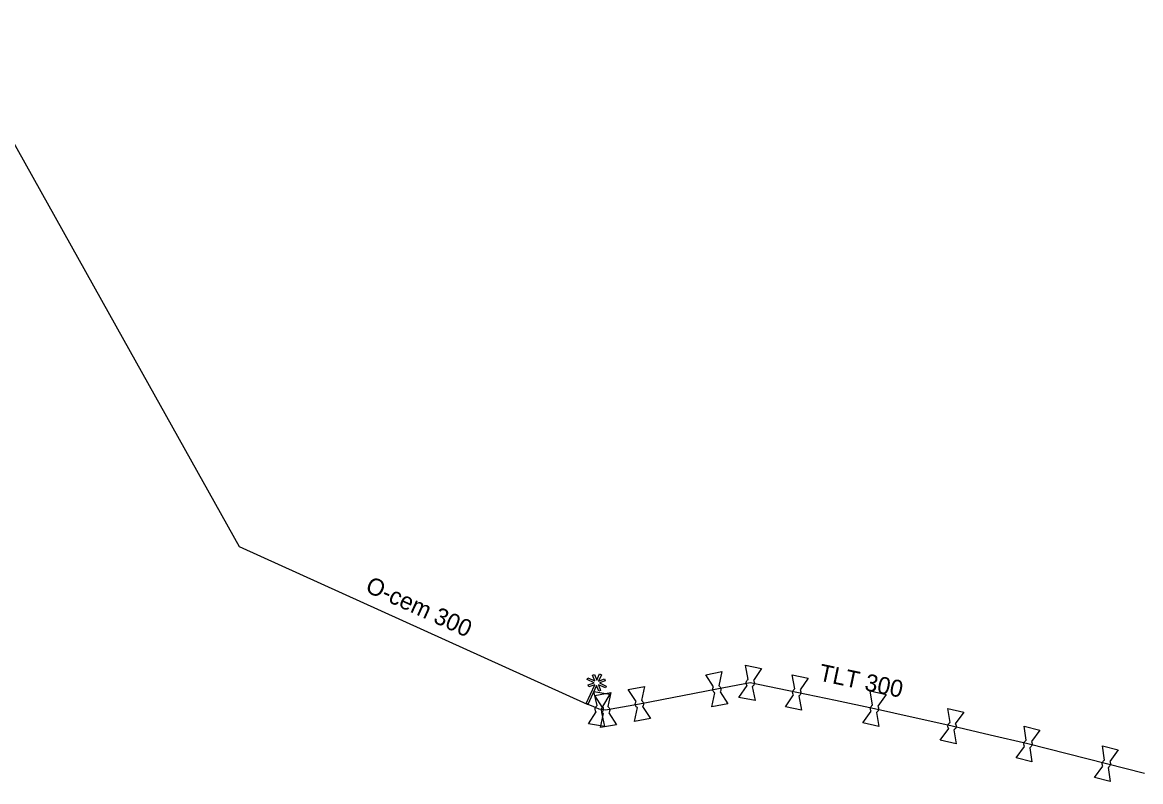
# Model space of a CAD drawing. Extents: x -638315 to -636370, y -1116147 to -1115110.
# Drawn here: x -637339.1 to -637253.7, y -1116037.8 to -1115979.8 of the extents above; entities that cross this region are included whole.
import ezdxf

# ---------------------------------------------------------------- set-up
doc = ezdxf.new("R2010")
doc.units = 0
for name, color, linetype in [('Default', 7, 'Continuous'), ('VP Lomový bod', 7, 'Continuous'), ('VP Změna materiálu', 7, 'Continuous'), ('VP Řad', 7, 'Continuous'), ('VP Řad - popis', 7, 'Continuous')]:
    doc.layers.add(name, color=color, linetype=linetype)

msp = doc.modelspace()

# ---------------------------------------------------------------- linework, layer by layer
at = {"layer": 'Default'}
for points in [[(-637286.238, -1116031.042), (-637286.282, -1116031.016), (-637286.317, -1116030.975), (-637286.372, -1116030.908), (-637286.387, -1116030.828), (-637286.402, -1116030.747), (-637286.375, -1116030.668), (-637286.357, -1116030.616), (-637286.324, -1116030.575)], [(-637285.923, -1116030.5), (-637285.878, -1116030.526), (-637285.842, -1116030.568), (-637285.788, -1116030.632), (-637285.773, -1116030.712), (-637285.758, -1116030.793), (-637285.786, -1116030.875), (-637285.802, -1116030.925), (-637285.836, -1116030.966)], [(-637283.778, -1116030.483), (-637283.81, -1116030.441), (-637283.827, -1116030.39), (-637283.853, -1116030.308), (-637283.836, -1116030.228), (-637283.82, -1116030.148), (-637283.765, -1116030.084), (-637283.729, -1116030.043), (-637283.683, -1116030.017)], [(-637283.283, -1116030.098), (-637283.25, -1116030.14), (-637283.234, -1116030.192), (-637283.207, -1116030.272), (-637283.224, -1116030.352), (-637283.24, -1116030.432), (-637283.297, -1116030.498), (-637283.331, -1116030.538), (-637283.378, -1116030.564)], [(-637280.23, -1116031.201), (-637280.261, -1116031.159), (-637280.278, -1116031.108), (-637280.303, -1116031.026), (-637280.286, -1116030.946), (-637280.269, -1116030.866), (-637280.213, -1116030.802), (-637280.177, -1116030.761), (-637280.131, -1116030.736)], [(-637279.732, -1116030.82), (-637279.699, -1116030.862), (-637279.683, -1116030.914), (-637279.657, -1116030.994), (-637279.674, -1116031.074), (-637279.691, -1116031.154), (-637279.749, -1116031.22), (-637279.783, -1116031.26), (-637279.83, -1116031.285)], [(-637295.301, -1116032.482), (-637295.334, -1116032.442), (-637295.353, -1116032.392), (-637295.382, -1116032.31), (-637295.368, -1116032.23), (-637295.355, -1116032.149), (-637295.302, -1116032.083), (-637295.268, -1116032.041), (-637295.223, -1116032.013)], [(-637294.821, -1116032.079), (-637294.786, -1116032.119), (-637294.768, -1116032.171), (-637294.738, -1116032.25), (-637294.752, -1116032.33), (-637294.765, -1116032.411), (-637294.819, -1116032.479), (-637294.852, -1116032.521), (-637294.897, -1116032.548)], [(-637294.73, -1116032.63), (-637294.775, -1116032.604), (-637294.809, -1116032.563), (-637294.863, -1116032.495), (-637294.878, -1116032.415), (-637294.892, -1116032.334), (-637294.864, -1116032.255), (-637294.846, -1116032.203), (-637294.812, -1116032.163)], [(-637294.411, -1116032.091), (-637294.365, -1116032.118), (-637294.33, -1116032.16), (-637294.277, -1116032.225), (-637294.262, -1116032.305), (-637294.248, -1116032.386), (-637294.277, -1116032.468), (-637294.294, -1116032.518), (-637294.328, -1116032.559)], [(-637292.147, -1116032.172), (-637292.192, -1116032.146), (-637292.227, -1116032.106), (-637292.282, -1116032.039), (-637292.297, -1116031.959), (-637292.312, -1116031.878), (-637292.285, -1116031.799), (-637292.268, -1116031.747), (-637292.235, -1116031.706)], [(-637291.834, -1116031.629), (-637291.788, -1116031.655), (-637291.753, -1116031.697), (-637291.698, -1116031.761), (-637291.683, -1116031.841), (-637291.668, -1116031.922), (-637291.695, -1116032.004), (-637291.712, -1116032.054), (-637291.745, -1116032.096)], [(-637274.302, -1116032.447), (-637274.333, -1116032.405), (-637274.349, -1116032.354), (-637274.373, -1116032.271), (-637274.355, -1116032.192), (-637274.337, -1116032.112), (-637274.28, -1116032.049), (-637274.244, -1116032.009), (-637274.197, -1116031.984)], [(-637273.799, -1116032.074), (-637273.767, -1116032.116), (-637273.752, -1116032.168), (-637273.727, -1116032.249), (-637273.745, -1116032.328), (-637273.763, -1116032.408), (-637273.821, -1116032.473), (-637273.856, -1116032.512), (-637273.903, -1116032.537)], [(-637268.384, -1116033.775), (-637268.414, -1116033.733), (-637268.429, -1116033.682), (-637268.452, -1116033.598), (-637268.434, -1116033.519), (-637268.415, -1116033.439), (-637268.358, -1116033.377), (-637268.321, -1116033.337), (-637268.274, -1116033.313)], [(-637267.877, -1116033.406), (-637267.846, -1116033.449), (-637267.83, -1116033.501), (-637267.807, -1116033.582), (-637267.825, -1116033.661), (-637267.844, -1116033.741), (-637267.903, -1116033.805), (-637267.938, -1116033.844), (-637267.985, -1116033.868)], [(-637262.587, -1116035.131), (-637262.617, -1116035.088), (-637262.631, -1116035.036), (-637262.653, -1116034.953), (-637262.633, -1116034.873), (-637262.613, -1116034.794), (-637262.555, -1116034.733), (-637262.517, -1116034.694), (-637262.47, -1116034.67)], [(-637262.074, -1116034.77), (-637262.044, -1116034.813), (-637262.029, -1116034.866), (-637262.007, -1116034.947), (-637262.027, -1116035.027), (-637262.047, -1116035.106), (-637262.107, -1116035.169), (-637262.143, -1116035.207), (-637262.191, -1116035.231)], [(-637256.608, -1116036.64), (-637256.637, -1116036.597), (-637256.652, -1116036.546), (-637256.673, -1116036.462), (-637256.653, -1116036.383), (-637256.633, -1116036.303), (-637256.574, -1116036.243), (-637256.536, -1116036.203), (-637256.489, -1116036.18)], [(-637256.094, -1116036.281), (-637256.063, -1116036.324), (-637256.049, -1116036.377), (-637256.027, -1116036.458), (-637256.047, -1116036.537), (-637256.067, -1116036.617), (-637256.128, -1116036.679), (-637256.164, -1116036.718), (-637256.211, -1116036.741)]]:
    msp.add_open_spline(points, degree=3, dxfattribs=at)
at = {"layer": 'VP Lomový bod'}
for points in [[(-637283.683, -1116030.017), (-637283.894, -1116028.941), (-637282.669, -1116029.189), (-637283.283, -1116030.098)], [(-637286.324, -1116030.575), (-637286.925, -1116029.657), (-637285.697, -1116029.426), (-637285.923, -1116030.5)], [(-637280.131, -1116030.736), (-637280.334, -1116029.658), (-637279.111, -1116029.916), (-637279.732, -1116030.82)], [(-637292.235, -1116031.706), (-637292.839, -1116030.79), (-637291.611, -1116030.555), (-637291.834, -1116031.629)], [(-637283.166, -1116031.639), (-637284.391, -1116031.391), (-637283.778, -1116030.483)], [(-637283.378, -1116030.564), (-637283.166, -1116031.639)], [(-637295.223, -1116032.013), (-637295.475, -1116030.946), (-637294.242, -1116031.147), (-637294.821, -1116032.079)], [(-637294.812, -1116032.163), (-637295.405, -1116031.239), (-637294.174, -1116031.02), (-637294.411, -1116032.091)], [(-637285.235, -1116031.883), (-637286.463, -1116032.114), (-637286.238, -1116031.042)], [(-637285.836, -1116030.966), (-637285.235, -1116031.883)], [(-637279.626, -1116032.362), (-637280.849, -1116032.104), (-637280.23, -1116031.201)], [(-637279.83, -1116031.285), (-637279.626, -1116032.362)], [(-637274.197, -1116031.984), (-637274.386, -1116030.903), (-637273.166, -1116031.177), (-637273.799, -1116032.074)], [(-637291.141, -1116033.01), (-637292.369, -1116033.245), (-637292.147, -1116032.172)], [(-637291.745, -1116032.096), (-637291.141, -1116033.01)], [(-637268.274, -1116033.313), (-637268.453, -1116032.23), (-637267.236, -1116032.516), (-637267.877, -1116033.406)], [(-637294.645, -1116033.614), (-637295.878, -1116033.413), (-637295.301, -1116032.482)], [(-637293.735, -1116033.481), (-637294.966, -1116033.7), (-637294.73, -1116032.63)], [(-637294.897, -1116032.548), (-637294.645, -1116033.614)], [(-637294.328, -1116032.559), (-637293.735, -1116033.481)], [(-637273.714, -1116033.617), (-637274.934, -1116033.343), (-637274.302, -1116032.447)], [(-637273.903, -1116032.537), (-637273.714, -1116033.617)], [(-637267.806, -1116034.95), (-637269.023, -1116034.664), (-637268.384, -1116033.775)], [(-637267.985, -1116033.868), (-637267.806, -1116034.95)], [(-637262.47, -1116034.67), (-637262.63, -1116033.585), (-637261.418, -1116033.891), (-637262.074, -1116034.77)], [(-637262.03, -1116036.315), (-637263.242, -1116036.009), (-637262.587, -1116035.131)], [(-637262.191, -1116035.231), (-637262.03, -1116036.315)], [(-637256.489, -1116036.18), (-637256.647, -1116035.094), (-637255.435, -1116035.403), (-637256.094, -1116036.281)], [(-637256.053, -1116037.826), (-637257.265, -1116037.517), (-637256.608, -1116036.64)], [(-637256.211, -1116036.741), (-637256.053, -1116037.826)]]:
    msp.add_lwpolyline(points, dxfattribs=at)
at = {"layer": 'VP Změna materiálu'}
msp.add_lwpolyline([(-637295.25, -1116030.083), (-637295.028, -1116029.591), (-637294.886, -1116029.656), (-637295.106, -1116030.143), (-637294.668, -1116029.977), (-637294.613, -1116030.123), (-637295.049, -1116030.288), (-637294.524, -1116030.526), (-637294.588, -1116030.668), (-637295.122, -1116030.426), (-637294.954, -1116030.87), (-637295.099, -1116030.924), (-637295.264, -1116030.491), (-637295.917, -1116031.933), (-637296.059, -1116031.869), (-637295.404, -1116030.422), (-637295.845, -1116030.589), (-637295.9, -1116030.443), (-637295.457, -1116030.275), (-637295.989, -1116030.034), (-637295.925, -1116029.891), (-637295.401, -1116030.129), (-637295.564, -1116029.694), (-637295.418, -1116029.64), (-637295.25, -1116030.083)], dxfattribs=at)
at = {"layer": 'VP Řad'}
for points in [[(-637659.447, -1115386.602), (-637652.176, -1115399.688), (-637606.77, -1115484.33), (-637550.22, -1115593.27), (-637494.64, -1115698.79), (-637438.33, -1115805.63), (-637381.21, -1115914.75), (-637331.344, -1116004.103), (-637322.54, -1116019.88), (-637295.99, -1116031.9)], [(-637253.43, -1116037.205), (-637256.35, -1116036.46), (-637259.34, -1116035.705), (-637262.33, -1116034.95), (-637265.23, -1116034.27), (-637268.13, -1116033.59), (-637269.813, -1116033.212), (-637271.09, -1116032.925), (-637274.05, -1116032.26), (-637277.015, -1116031.635), (-637279.98, -1116031.01), (-637283.53, -1116030.29), (-637286.08, -1116030.77), (-637291.99, -1116031.9), (-637294.57, -1116032.36), (-637295.06, -1116032.28), (-637295.525, -1116032.09), (-637295.99, -1116031.9)]]:
    msp.add_lwpolyline(points, dxfattribs=at)

# ---------------------------------------------------------------- texts
at = {"layer": 'VP Řad - popis'}
for s, rotation, p in [('O-cem 300', 335.64228, (-637312.989, -1116023.286)), ('TLT 300', 348.09673, (-637278.364, -1116030.092))]:
    msp.add_text(s, height=1.3, rotation=rotation, dxfattribs=at).set_placement(p)

doc.saveas('drawing.dxf')
